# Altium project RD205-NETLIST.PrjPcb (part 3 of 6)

## Sheet 2.SchDoc
size 420 x 297 mm
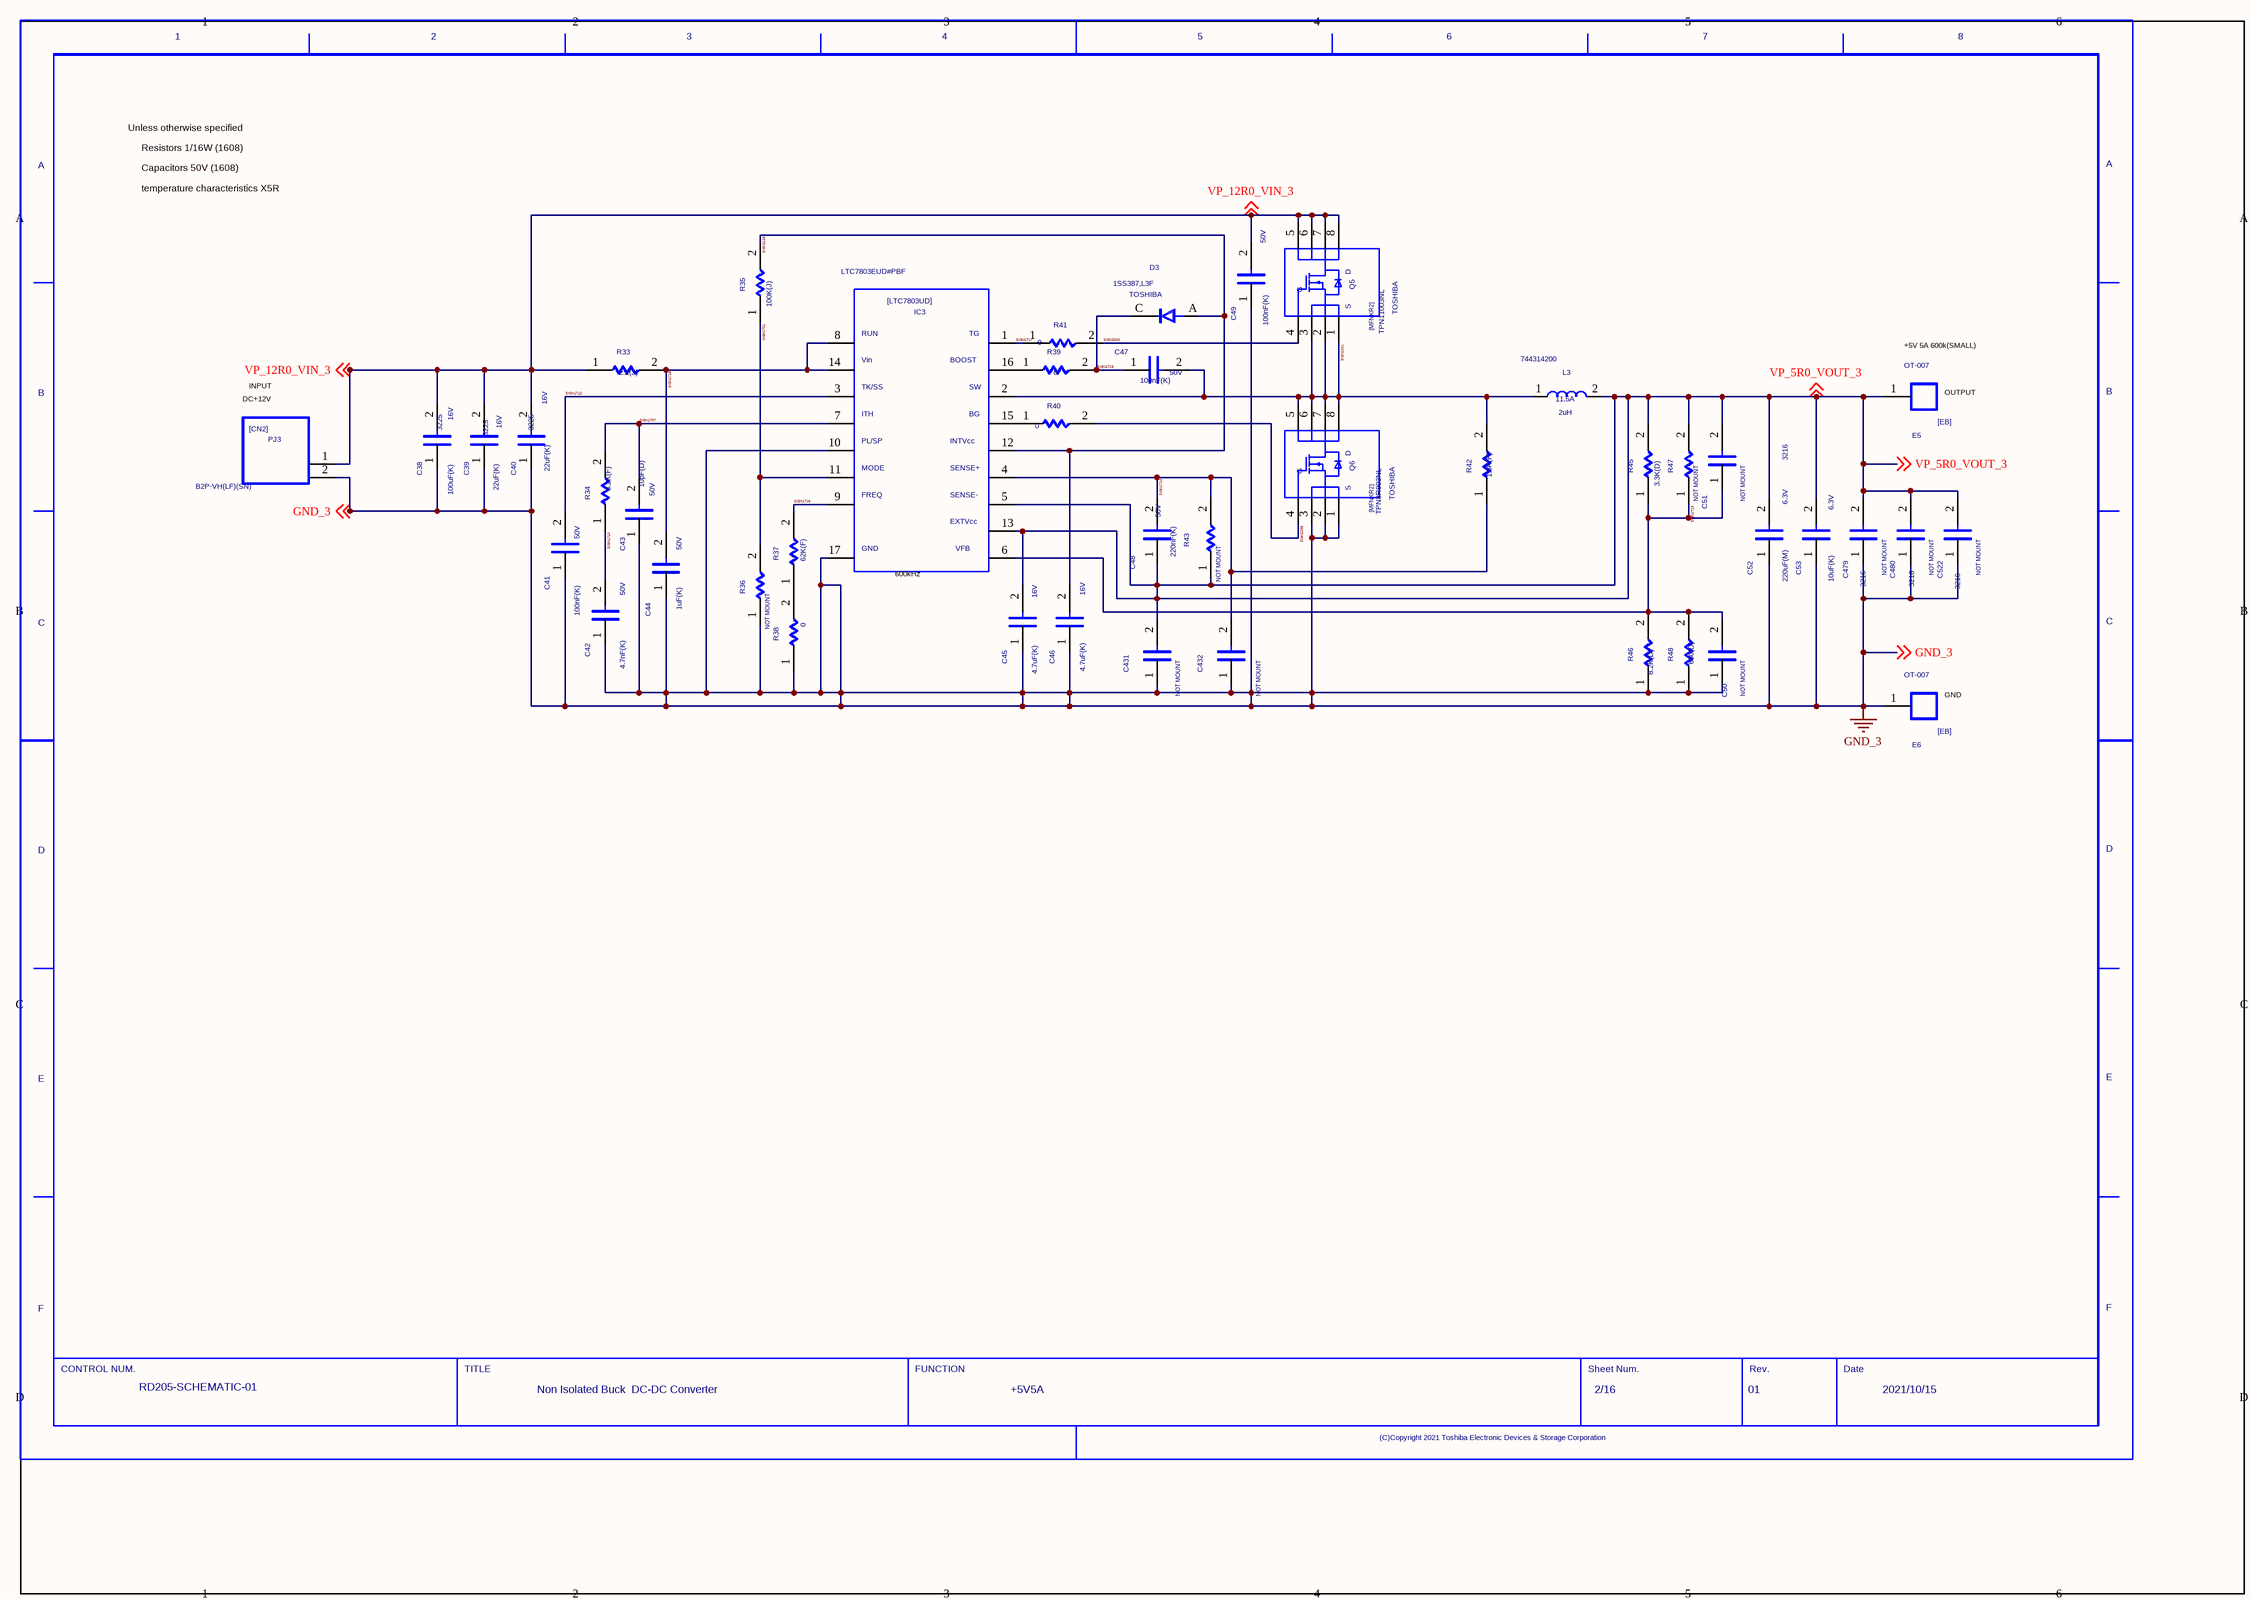
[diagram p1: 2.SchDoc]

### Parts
(Parts that share a designator on the sheet are numbered #1, #2 ... from top to bottom, then left to right.)
C38  SIZECODESMD: 3225  VAL2: 16V  VAL1: 100uF(K)  (hidden comment: C)
C39  SIZECODESMD: 3225  VAL2: 16V  VAL1: 22uF(K)  (hidden comment: C)
C40  SIZECODESMD: 3225  VAL2: 16V  VAL1: 22uF(K)  (hidden comment: C)
C41  VAL2: 50V  VAL1: 100nF(K)  (hidden comment: C)
C42  VAL2: 50V  VAL1: 4.7nF(K)  (hidden comment: C)
C43  VAL2: 50V  VAL1: 10pF(D)  (hidden comment: C)
C44  VAL2: 50V  VAL1: 1uF(K)  (hidden comment: C)
C45  VAL2: 16V  VAL1: 4.7uF(K)  (hidden comment: C)
C46  VAL2: 16V  VAL1: 4.7uF(K)  (hidden comment: C)
C47  VAL2: 50V  VAL1: 100nF(K)  (hidden comment: C)
C48  VAL2: 50V  VAL1: 220nF(K)  (hidden comment: C)
C49  VAL2: 50V  VAL1: 100nF(K)  (hidden comment: C)
C50  NOTMOUNT: NOT MOUNT  (hidden comment: C)
C51  NOTMOUNT: NOT MOUNT  (hidden comment: C)
C52  SIZECODESMD: 3216  VAL2: 6.3V  VAL1: 220uF(M)  (hidden comment: C)
C53  VAL2: 6.3V  VAL1: 10uF(K)  (hidden comment: C)
C431  NOTMOUNT: NOT MOUNT  (hidden comment: C)
C432  NOTMOUNT: NOT MOUNT  (hidden comment: C)
C479  NOTMOUNT: NOT MOUNT  SIZECODESMD: 3216  (hidden comment: C)
C480  NOTMOUNT: NOT MOUNT  SIZECODESMD: 3216  (hidden comment: C)
C522  NOTMOUNT: NOT MOUNT  SIZECODESMD: 3216  (hidden comment: C)
D3  USERCOMPTEXT3: TOSHIBA  VAL3: 1SS387,L3F  (hidden comment: D)
E5  VAL3: OT-007  (hidden comment: EB)
E6  VAL3: OT-007  (hidden comment: EB)
IC3  VAL3: LTC7803EUD#PBF  (hidden comment: LTC7803UD)
L3  VAL3: 744314200  VAL2: 11.5A  VAL1: 2uH  (hidden comment: L)
PJ3  VAL3: B2P-VH(LF)(SN)  (hidden comment: CN2)
Q5  USERCOMPTEXT3: TOSHIBA  VAL3: TPN11003NL  (hidden comment: MFNKR2)
Q6  USERCOMPTEXT3: TOSHIBA  VAL3: TPN8R903NL  (hidden comment: MFNKR2)
R33  VAL1: 2.2(J)  (hidden comment: R)
R34  VAL1: 8.2K(F)  (hidden comment: R)
R35  VAL1: 100K(J)  (hidden comment: R)
R36  NOTMOUNT: NOT MOUNT  (hidden comment: R)
R37  VAL1: 62K(F)  (hidden comment: R)
R38  VAL1: 0  (hidden comment: R)
R39  VAL1: 0  (hidden comment: R)
R40  VAL1: 0  (hidden comment: R)
R41  VAL1: 0  (hidden comment: R)
R42  VAL1: 1.5K(F)  (hidden comment: R)
R43  NOTMOUNT: NOT MOUNT  (hidden comment: R)
R45  VAL1: 3.3K(D)  (hidden comment: R)
R46  VAL1: 8.2K(D)  (hidden comment: R)
R47  NOTMOUNT: NOT MOUNT  (hidden comment: R)
R48  VAL1: 680(D)  (hidden comment: R)
U?#2  DATE: 2021/10/15  SHEETNUMBER: 2/16  TITLE: Non Isolated Buck / DC-DC Converter  REVISION: 01  DRAWINGNUMBER: RD205-SCHEMATIC-01  FUNCTION: +5V5A  (hidden comment: WAKU_DEF100)

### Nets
GND_3: C38.1 C39.1 C40.1 C41.1 C42.1 C43.1 C44.1 C45.1 C46.1 C49.1 C50.1 C52.1 C53.1 C431.1 C432.1 C479.1 C480.1 C522.1 E6.1 IC3.10 IC3.17 PJ3.2 Q6.1 Q6.2 Q6.3 R36.1 R38.1 R46.1 R48.1 ; off-sheet GND_3
SIGN1701: IC3.11 R35.1 R36.2
SIGN1707: C43.2 IC3.7 R34.2
SIGN1710: C42.2 R34.1
SIGN1712: C41.2 IC3.3
SIGN1713: C50.2 C51.1 IC3.6 R45.1 R46.2 R47.1 R48.2
SIGN1714: C48.2 C432.2 IC3.4 R42.1 R43.2
SIGN1716: IC3.9 R37.2
SIGN1717: IC3.1 R41.1
SIGN1718: C44.2 IC3.8 IC3.14 R33.2
SIGN1719: C47.1 D3.C R39.2
SIGN2128: C46.2 D3.A IC3.12 R35.2
SIGN2239: Q6.4 R40.2
SIGN2240: Q5.4 R41.2
SIGN2241: C47.2 IC3.2 L3.1 Q5.1 Q5.2 Q5.3 Q6.5 Q6.6 Q6.7 Q6.8 R42.2
VP_5R0_VOUT_3: C45.2 C48.1 C51.2 C52.2 C53.2 C431.2 C479.2 C480.2 C522.2 E5.1 IC3.5 IC3.13 L3.2 R43.1 R45.2 R47.2 ; off-sheet VP_5R0_VOUT_3
VP_12R0_VIN_3: C38.2 C39.2 C40.2 C49.2 PJ3.1 Q5.5 Q5.6 Q5.7 Q5.8 R33.1 ; off-sheet VP_12R0_VIN_3
NetIC3_15: IC3.15 R40.1
NetIC3_16: IC3.16 R39.1
NetR37_1: R37.1 R38.2

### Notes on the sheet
- Unless otherwise specified
- Capacitors 50V (1608)
- Resistors 1/16W (1608)
- temperature characteristics X5R
- DC+12V
- INPUT
- (near E5) +5V 5A 600k(SMALL)
- (near E5) OUTPUT
- (near IC3) 600kHz
- (near E6) GND

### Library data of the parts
C38 = C_Dup1: SQ_PART_MODEL: CON_100n; FNPARTSNAMEG: CHIP CERAMIC CAPACITOR (3225); USEINPARTSLIST: YES; OriginalSymbolOrigin: (2540,7620); MFSOLDERINGPROP: .; TEMPCHARACTERI2: B; MFFORMINGDIVP: KC; OUMECLASSIFICATION: セラミックコンデンサ; MFMOUNTSYMBOLP: 90; CDMASTERCADCELG: DC903A; PCODE: P03276001115; FNCLASSCODEG: P03-03; MAXGCOUNT: 1; RATEDVOLTAGE: 250; COMPONENTNAME: G36030160049; OUMEMAKER: KYC 京セラ; MFPACKAGEMETHOP: S; NOMINALCAPACITA: 100n; OUMEMAKERKATAMEI: CF32W5R104K250AT; CAPACITANCETOLE: K
C39 C40 = C_Dup1: SQ_PART_MODEL: CON_22u; FNPARTSNAMEG: CHIP CERAMIC CAPACITOR (3225); USEINPARTSLIST: YES; OriginalSymbolOrigin: (2540,7620); MFSOLDERINGPROP: .; TEMPCHARACTERI2: B; MFFORMINGDIVP: KC; OUMECLASSIFICATION: セラミックコンデンサ; MFMOUNTSYMBOLP: 80; CDMASTERCADCELG: DC903A; PCODE: P03043035626; FNCLASSCODEG: P03-03; MAXGCOUNT: 1; RATEDVOLTAGE: 6.3; COMPONENTNAME: G36030119054; OUMEMAKER: TYD 太陽誘電; MFPACKAGEMETHOP: S; NOMINALCAPACITA: 22u; OUMEMAKERKATAMEI: JMK325BJ226KM-T; CAPACITANCETOLE: K
C41 C47 C49 = C_Dup1: SQ_PART_MODEL: CON_100n; FNPARTSNAMEG: CHIP CERAMIC CAPACITOR (1608); USEINPARTSLIST: YES; OriginalSymbolOrigin: (2540,7620); MFSOLDERINGPROP: .; TEMPCHARACTERI2: B; MFFORMINGDIVP: KC; OUMECLASSIFICATION: セラミックコンデンサ; SIZECODESMD: 1608; MFMOUNTSYMBOLP: 80; CDMASTERCADCELG: C8100E; PCODE: P03B000000E4; FNCLASSCODEG: P03-03; MAXGCOUNT: 1; RATEDVOLTAGE: 16; COMPONENTNAME: GDM030000598; OUMEMAKER: MRT 村田製作所; MFPACKAGEMETHOP: S; NOMINALCAPACITA: 100n; OUMEMAKERKATAMEI: GRM188B11C104KA01C; CAPACITANCETOLE: K
C42 = C_Dup1: SQ_PART_MODEL: CON_4.7n; FNPARTSNAMEG: CHIP CERAMIC CAPACITOR (1608); USEINPARTSLIST: YES; OriginalSymbolOrigin: (2540,7620); TOLERANCE: K; ASIMVALUE: 4.7N; MFSOLDERINGPROP: .; TEMPCHARACTERI2: B; MFFORMINGDIVP: KC; OUMECLASSIFICATION: セラミックコンデンサ; SIZECODESMD: 1608; MFMOUNTSYMBOLP: 80; CDMASTERCADCELG: C8100E; PCODE: P03039090226; FNCLASSCODEG: P03-03; MAXGCOUNT: 1; RATEDVOLTAGE: 50; COMPONENTNAME: G36030011280; OUMEMAKER: MRT 村田製作所; MFPACKAGEMETHOP: S; OUMEMAKERKATAMEI: GRM39B472K50PT
C43 = C_Dup1: SQ_PART_MODEL: CON_10p; FNPARTSNAMEG: CHIP CERAMIC CAPACITOR (1608); USEINPARTSLIST: YES; OriginalSymbolOrigin: (2540,7620); TOLERANCE: D; ASIMVALUE: 10P; MFSOLDERINGPROP: .; TEMPCHARACTERI2: CH; MFFORMINGDIVP: KC; OUMECLASSIFICATION: セラミックコンデンサ; SIZECODESMD: 1608; MFMOUNTSYMBOLP: 80; CDMASTERCADCELG: C8100E; PCODE: P03039185229; FNCLASSCODEG: P03-03; MAXGCOUNT: 1; RATEDVOLTAGE: 50; COMPONENTNAME: G36030011013; OUMEMAKER: MRT 村田製作所; MFPACKAGEMETHOP: S; OUMEMAKERKATAMEI: GRM39CH100D50PT
C44 = C_Dup1: SQ_PART_MODEL: CON_1u; FNPARTSNAMEG: CHIP CERAMIC CAPACITOR (1608); USEINPARTSLIST: YES; OriginalSymbolOrigin: (2540,7620); MFSOLDERINGPROP: .; TEMPCHARACTERI2: B; MFFORMINGDIVP: KC; OUMECLASSIFICATION: セラミックコンデンサ; SIZECODESMD: 1608; MFMOUNTSYMBOLP: 80; CDMASTERCADCELG: C8100E; PCODE: P03039ACE122; FNCLASSCODEG: P03-03; MAXGCOUNT: 1; RATEDVOLTAGE: 6.3; COMPONENTNAME: G36030104159; OUMEMAKER: KYC 京セラ; MFPACKAGEMETHOP: S; NOMINALCAPACITA: 1u; OUMEMAKERKATAMEI: CM105B105K06ATN; CAPACITANCETOLE: K
C45 = C_Dup1: SQ_PART_MODEL: CON_4.7u; FNPARTSNAMEG: CHIP CERAMIC CAPACITOR (1608); USEINPARTSLIST: YES; OriginalSymbolOrigin: (2540,7620); PCODE: P03B000000MS; MFSOLDERINGPROP: .; TEMPCHARACTERI2: B; MFFORMINGDIVP: KC; OUMECLASSIFICATION: セラミックコンデンサ; SIZECODESMD: 1608; MFMOUNTSYMBOLP: 80; CDMASTERCADCELG: C8100E; FNCLASSCODEG: P03-03; MAXGCOUNT: 1; RATEDVOLTAGE: 4; COMPONENTNAME: GDM030000053; OUMEMAKER: KYC 京セラ; MFPACKAGEMETHOP: S; NOMINALCAPACITA: 4.7u; OUMEMAKERKATAMEI: CM105B475M04AT; CAPACITANCETOLE: M
C46 = C_Dup1: SQ_PART_MODEL: CON_4.7u; FNPARTSNAMEG: CHIP CERAMIC CAPACITOR (1608); USEINPARTSLIST: YES; OriginalSymbolOrigin: (2540,7620); MFSOLDERINGPROP: .; TEMPCHARACTERI2: B; MFFORMINGDIVP: KC; OUMECLASSIFICATION: セラミックコンデンサ; SIZECODESMD: 1608; MFMOUNTSYMBOLP: 80; CDMASTERCADCELG: C8100E; PCODE: P03B000000MS; FNCLASSCODEG: P03-03; MAXGCOUNT: 1; RATEDVOLTAGE: 4; COMPONENTNAME: GDM030000053; OUMEMAKER: KYC 京セラ; MFPACKAGEMETHOP: S; NOMINALCAPACITA: 4.7u; OUMEMAKERKATAMEI: CM105B475M04AT; CAPACITANCETOLE: M
C48 = C_Dup1: SQ_PART_MODEL: CON_220n; FNPARTSNAMEG: CHIP CERAMIC CAPACITOR (1608); PARTCOMMENT: 代表セル<KC0008> がフットプリントに登録されていません。; USEINPARTSLIST: YES; OriginalSymbolOrigin: (2540,7620); MFSOLDERINGPROP: .; TEMPCHARACTERI2: B; MFFORMINGDIVP: KC; OUMECLASSIFICATION: セラミックコンデンサ; SIZECODESMD: 1608; MFMOUNTSYMBOLP: 80; CDMASTERCADCELG: KC0008; PCODE: P03B000001L3; FNCLASSCODEG: P03-03; MAXGCOUNT: 1; RATEDVOLTAGE: 16; COMPONENTNAME: GDM030001129; OUMEMAKER: MRT 村田製作所; MFPACKAGEMETHOP: S; NOMINALCAPACITA: 220n; OUMEMAKERKATAMEI: GRM188B11C224KA01D; CAPACITANCETOLE: K
C50 C51 = C_Dup1: SQ_PART_MODEL: CON_100p; FNPARTSNAMEG: CHIP CERAMIC CAPACITOR (1608); USEINPARTSLIST: YES; OriginalSymbolOrigin: (2540,7620); TOLERANCE: J; ASIMVALUE: 100P; MFSOLDERINGPROP: .; TEMPCHARACTERI2: CH; MFFORMINGDIVP: KC; OUMECLASSIFICATION: セラミックコンデンサ; SIZECODESMD: 1608; MFMOUNTSYMBOLP: 80; CDMASTERCADCELG: C8100E; PCODE: P03039177125; FNCLASSCODEG: P03-03; MAXGCOUNT: 1; RATEDVOLTAGE: 50; COMPONENTNAME: G36030011365; OUMEMAKER: KYC 京セラ; MFPACKAGEMETHOP: S; OUMEMAKERKATAMEI: CM105CH101J50AT; VAL2: 50V; VAL1: 100pF(J)
C52 = C_Dup1: SQ_PART_MODEL: CON_22u; FNPARTSNAMEG: CHIP CERAMIC CAPACITOR (3216); USEINPARTSLIST: YES; OriginalSymbolOrigin: (2540,7620); MFSOLDERINGPROP: .; TEMPCHARACTERI2: B; MFFORMINGDIVP: KC; OUMECLASSIFICATION: セラミックコンデンサ; MFMOUNTSYMBOLP: 80; CDMASTERCADCELG: DC901A; PCODE: P03B0000004V; FNCLASSCODEG: P03-03; MAXGCOUNT: 1; RATEDVOLTAGE: 6.3; COMPONENTNAME: GDM030000020; OUMEMAKER: KYC 京セラ; MFPACKAGEMETHOP: S; NOMINALCAPACITA: 22u; OUMEMAKERKATAMEI: CM316B226M06AT; CAPACITANCETOLE: M
C53 = C_Dup1: SQ_PART_MODEL: CON_1u; FNPARTSNAMEG: CHIP CERAMIC CAPACITOR (1608); PARTCOMMENT: 代表セル<KC0008> がフットプリントに登録されていません。; USEINPARTSLIST: YES; OriginalSymbolOrigin: (2540,7620); MFSOLDERINGPROP: .; TEMPCHARACTERI2: B; MFPACKAGEMETHOP: S; MFFORMINGDIVP: KC; MFMOUNTSYMBOLP: 80; PCODE: P03B000000ZQ; OUMECLASSIFICATION: セラミックコンデンサ; SIZECODESMD: 1608; CDMASTERCADCELG: KC0008; FNCLASSCODEG: P03-03; MAXGCOUNT: 1; RATEDVOLTAGE: 6.3; COMPONENTNAME: GDM030000202; OUMEMAKER: MRT 村田製作所; NOMINALCAPACITA: 1u; OUMEMAKERKATAMEI: GRM185B10J105KE21D; CAPACITANCETOLE: K
C431 C432 = C_Dup1: SQ_PART_MODEL: CON_220n; FNPARTSNAMEG: CHIP CERAMIC CAPACITOR (1608); PARTCOMMENT: 代表セル<KC0008> がフットプリントに登録されていません。; USEINPARTSLIST: YES; OriginalSymbolOrigin: (2540,7620); MFSOLDERINGPROP: .; TEMPCHARACTERI2: B; MFFORMINGDIVP: KC; OUMECLASSIFICATION: セラミックコンデンサ; SIZECODESMD: 1608; MFMOUNTSYMBOLP: 80; CDMASTERCADCELG: KC0008; PCODE: P03B000001L3; FNCLASSCODEG: P03-03; MAXGCOUNT: 1; RATEDVOLTAGE: 16; COMPONENTNAME: GDM030001129; OUMEMAKER: MRT 村田製作所; MFPACKAGEMETHOP: S; NOMINALCAPACITA: 220n; OUMEMAKERKATAMEI: GRM188B11C224KA01D; VAL2: 16V; VAL1: 220nF(K); CAPACITANCETOLE: K
C479 C480 C522 = C_Dup1: SQ_PART_MODEL: CON_22u; FNPARTSNAMEG: CHIP CERAMIC CAPACITOR (3216); USEINPARTSLIST: YES; OriginalSymbolOrigin: (2540,7620); MFSOLDERINGPROP: .; TEMPCHARACTERI2: B; MFFORMINGDIVP: KC; OUMECLASSIFICATION: セラミックコンデンサ; MFMOUNTSYMBOLP: 80; CDMASTERCADCELG: DC901A; PCODE: P03B0000004V; FNCLASSCODEG: P03-03; MAXGCOUNT: 1; RATEDVOLTAGE: 6.3; COMPONENTNAME: GDM030000020; OUMEMAKER: KYC 京セラ; MFPACKAGEMETHOP: S; NOMINALCAPACITA: 22u; OUMEMAKERKATAMEI: CM316B226M06AT; VAL2: 6.3V; VAL1: 22uF(M); CAPACITANCETOLE: M
D3 = D_Dup1: FNPARTSNAMEG: DIODE; USEINPARTSLIST: YES; PARTNAME: GDM420000143; SAVEAREA0: -565,-171,12979,8058; SAVECOUNT: 1; OriginalSymbolOrigin: (2540,5080); FORWARDVOLTAGEM: 0; MAXREVERSEVOLTA: 80; COMPONENTNAME: GDM420000143_package; MFSOLDERINGPROP: .; OUMEMAKER: TSB 東芝（ＹＰＳＳ）; QUADMODEL: dummymodel; MFPACKAGEMETHOP: S; MFFORMINGDIVP: MM; MOUNTINGFORMSMD: SMD; OUMECLASSIFICATION: 小信号ダイオード; OUMEMAKERKATAMEI: 1SS387(TPH3,F); CDMASTERCADCELG: D8101D; PCODE: P42B0000008E; FNCLASSCODEG: P42-01
E5 E6 = EB_Dup1: FNPARTSNAMEG: TERMINAL; USEINPARTSLIST: YES; PARTNAME: 5P9L1232P001; OUMEPARTTYPE: TB; OriginalSymbolOrigin: (2540,12700); COMPONENTNAME: 5P9L1232P001_package; MAXGCOUNT: 1; MFSOLDERINGPROP: .; OUMEMAKER: オサダ; QUADMODEL: dummymodel; MFPACKAGEMETHOP: I; MFFORMINGDIVP: OD; OUMECLASSIFICATION: 端子台、端子板; CDMASTERCADCELG: DE0009; KIND: PBS; PCODE: P29045001117; TERMINALSTYLE: SC; FNCLASSCODEG: P29-01
IC3 = LTC7803UD: USEINPARTSLIST: YES; SAVECOUNT: 29; SAVEAREA0: -53177,0,89020,58420; TIME: 16:14:14; UPDATEUSER: q91866sr; UPDATETIME: 13:15:36; OriginalSymbolOrigin: (5080,55880); MAXGCOUNT: 1; COMPONENTNAME: LTC7803UD_LTC7803UD; OUMEMAKER: ANALOG DEVICES
L3 = L_Dup1: USEINPARTSLIST: YES; PARTNAME: 744311100; OriginalSymbolOrigin: (2540,5080); MAXGCOUNT: 1; COMPONENTNAME: L_L; OUMEMAKER: WURTH
PJ3 = CN2_Dup1: FNPARTSNAMEG: 3.96PITCH NYLON CONNECTOR; USEINPARTSLIST: YES; PARTNAME: G36220114012; OUMEPARTTYPE: CN; OriginalSymbolOrigin: (2540,15240); MAXGCOUNT: 1; RATEDCURRENT: 7; COMPONENTNAME: G36220114012_package; MFSOLDERINGPROP: .; OUMEMAKER: JST 日本圧着端子製造; NUMBEROFCONTACT: 2; QUADMODEL: dummymodel; MFPACKAGEMETHOP: I; MFFORMINGDIVP: CU; CONTACTPITCH: 3.96m; OUMEMAKERKATAMEI: B2P-VH; CDMASTERCADCELG: DPJ514; PCODE: P22346001114; TERMINALSTYLE: PW; FNCLASSCODEG: P22-10
Q5 Q6 = MFNKR2: USEINPARTSLIST: YES; PARTNAME: TPN1R603PL; SAVEAREA0: -9199,-39,32138,22820; TIME: 18:57:44; UPDATEUSER: q91866sr; UPDATETIME: 12:36:02; SAVECOUNT: 10; OriginalSymbolOrigin: (5080,20320); MAXGCOUNT: 1; COMPONENTNAME: MFNKR2_MFNKR2
R33 = R_Dup1: SQ_PART_MODEL: RES_2.2; FNPARTSNAMEG: CHIP RESISTOR (1608); USEINPARTSLIST: YES; OriginalSymbolOrigin: (5080,5080); TOLERANCE: J; ASIMVALUE: 2.2; MAXGCOUNT: 1; COMPONENTNAME: G36010011507; MFSOLDERINGPROP: .; OUMEMAKER: NAE 松下電子部品; MFPACKAGEMETHOP: S; MFFORMINGDIVP: KC; MOUNTINGFORMSMD: SMD; OUMECLASSIFICATION: 表面実装用固定抵抗器; MFMOUNTSYMBOLP: 80; POWERRATING: 63m; OUMEMAKERKATAMEI: ERJ3GEYJ2R2V; NUMBEROFELEMENT: 0; VAL2: 62.5mW; CDMASTERCADCELG: DR802R; PCODE: P01042157622; FNCLASSCODEG: P01-08
R34 = R_Dup1: SQ_PART_MODEL: RES_8.2K; FNPARTSNAMEG: CHIP RESISTOR (1608); USEINPARTSLIST: YES; OriginalSymbolOrigin: (5080,5080); TOLERANCE: F; ASIMVALUE: 8.2K; MAXGCOUNT: 1; COMPONENTNAME: G36010027188; MFSOLDERINGPROP: .; OUMEMAKER: KAM 釜屋電機; MFPACKAGEMETHOP: S; MFFORMINGDIVP: KC; MOUNTINGFORMSMD: SMD; OUMECLASSIFICATION: 表面実装用固定抵抗器; MFMOUNTSYMBOLP: 80; POWERRATING: 63m; OUMEMAKERKATAMEI: RMC1/16-822FTP; NUMBEROFELEMENT: 0; VAL2: 62.5mW; CDMASTERCADCELG: DR802R; PCODE: P01042507328; FNCLASSCODEG: P01-08
R35 = R_Dup1: SQ_PART_MODEL: RES_100K; FNPARTSNAMEG: CHIP RESISTOR (1608); USEINPARTSLIST: YES; OriginalSymbolOrigin: (5080,5080); TOLERANCE: J; ASIMVALUE: 100K; MFSOLDERINGPROP: .; MFPACKAGEMETHOP: S; MFFORMINGDIVP: KC; MOUNTINGFORMSMD: SMD; MFMOUNTSYMBOLP: 80; NUMBEROFELEMENT: 0; PCODE: P01042047220; MAXGCOUNT: 1; COMPONENTNAME: G36010011057; OUMEMAKER: HDK 北陸電気工業; OUMECLASSIFICATION: 表面実装用固定抵抗器; POWERRATING: 63m; OUMEMAKERKATAMEI: CR1/16 104JV; VAL2: 62.5mW; CDMASTERCADCELG: DR802R; FNCLASSCODEG: P01-08
R36 = R_Dup1: SQ_PART_MODEL: RES_10; FNPARTSNAMEG: CHIP RESISTOR (1608); USEINPARTSLIST: YES; OriginalSymbolOrigin: (5080,5080); TOLERANCE: F; ASIMVALUE: 10; MFSOLDERINGPROP: .; MFPACKAGEMETHOP: S; MFFORMINGDIVP: KC; MOUNTINGFORMSMD: SMD; MFMOUNTSYMBOLP: 80; NUMBEROFELEMENT: 0; PCODE: P01042036620; MAXGCOUNT: 1; COMPONENTNAME: G36010104063; OUMEMAKER: NAE 松下電子部品; OUMECLASSIFICATION: 表面実装用固定抵抗器; POWERRATING: 63m; OUMEMAKERKATAMEI: ERJ3GEYF100V; VAL2: 62.5mW; VAL1: 10(F); CDMASTERCADCELG: DR802R; FNCLASSCODEG: P01-08
R37 = R_Dup1: SQ_PART_MODEL: RES_62K; FNPARTSNAMEG: CHIP RESISTOR (1608); USEINPARTSLIST: YES; OriginalSymbolOrigin: (5080,5080); MAXGCOUNT: 1; TOLERANCE: F; COMPONENTNAME: G36010027355; MFSOLDERINGPROP: .; OUMEMAKER: HDK 北陸電気工業; MFPACKAGEMETHOP: S; MFFORMINGDIVP: KC; MOUNTINGFORMSMD: SMD; OUMECLASSIFICATION: 表面実装用固定抵抗器; ASIMVALUE: 62K; MFMOUNTSYMBOLP: 80; POWERRATING: 63m; OUMEMAKERKATAMEI: CR1/16 623FV; NUMBEROFELEMENT: 0; VAL2: 62.5mW; CDMASTERCADCELG: DR802R; PCODE: P01042441226; FNCLASSCODEG: P01-08
R38 = R_Dup1: SQ_PART_MODEL: RES_10; FNPARTSNAMEG: CHIP RESISTOR (1608); USEINPARTSLIST: YES; OriginalSymbolOrigin: (5080,5080); TOLERANCE: F; ASIMVALUE: 10; MAXGCOUNT: 1; COMPONENTNAME: G36010104063; MFSOLDERINGPROP: .; OUMEMAKER: NAE 松下電子部品; MFPACKAGEMETHOP: S; MFFORMINGDIVP: KC; MOUNTINGFORMSMD: SMD; OUMECLASSIFICATION: 表面実装用固定抵抗器; MFMOUNTSYMBOLP: 80; POWERRATING: 63m; OUMEMAKERKATAMEI: ERJ3GEYF100V; VAL2: 62.5mW; CDMASTERCADCELG: DR802R; PCODE: P01042036620; FNCLASSCODEG: P01-08
R39 = R_Dup1: SQ_PART_MODEL: RES_10; FNPARTSNAMEG: CHIP RESISTOR (1608); USEINPARTSLIST: YES; OriginalSymbolOrigin: (5080,5080); TOLERANCE: F; ASIMVALUE: 10; MFSOLDERINGPROP: .; MFPACKAGEMETHOP: S; MFFORMINGDIVP: KC; MOUNTINGFORMSMD: SMD; MFMOUNTSYMBOLP: 80; PCODE: P01042036620; MAXGCOUNT: 1; COMPONENTNAME: G36010104063; OUMEMAKER: NAE 松下電子部品; OUMECLASSIFICATION: 表面実装用固定抵抗器; POWERRATING: 63m; OUMEMAKERKATAMEI: ERJ3GEYF100V; VAL2: 62.5mW; CDMASTERCADCELG: DR802R; FNCLASSCODEG: P01-08
R40 R41 = R_Dup1: SQ_PART_MODEL: RES_10; FNPARTSNAMEG: CHIP RESISTOR (2012); USEINPARTSLIST: YES; OriginalSymbolOrigin: (5080,5080); MAXGCOUNT: 1; TOLERANCE: F; COMPONENTNAME: 5P9L1083P100; MFSOLDERINGPROP: .; OUMEMAKER: 北陸電気工業; MFPACKAGEMETHOP: S; MFFORMINGDIVP: KC; MOUNTINGFORMSMD: SMD; OUMECLASSIFICATION: 表面実装用固定抵抗器; ASIMVALUE: 10; MFMOUNTSYMBOLP: 90; POWERRATING: 100m; OUMEMAKERKATAMEI: CR1/10 100FV Pb(F); VAL2: 125mW; CDMASTERCADCELG: DR910A; PCODE: P01043091222; FNCLASSCODEG: P01-08
R42 = R_Dup1: SQ_PART_MODEL: RES_1.5K; FNPARTSNAMEG: CHIP RESISTOR (1608); USEINPARTSLIST: YES; OriginalSymbolOrigin: (5080,5080); TOLERANCE: F; ASIMVALUE: 1.5K; MAXGCOUNT: 1; COMPONENTNAME: G36010027232; MFSOLDERINGPROP: .; OUMEMAKER: HDK 北陸電気工業; MFPACKAGEMETHOP: S; MFFORMINGDIVP: KC; MOUNTINGFORMSMD: SMD; OUMECLASSIFICATION: 表面実装用固定抵抗器; MFMOUNTSYMBOLP: 80; POWERRATING: 63m; OUMEMAKERKATAMEI: CR1/16 152FV; NUMBEROFELEMENT: 0; VAL2: 62.5mW; CDMASTERCADCELG: DR802R; PCODE: P01042512223; FNCLASSCODEG: P01-08
R43 = R_Dup1: SQ_PART_MODEL: RES_8.2K; FNPARTSNAMEG: CHIP RESISTOR (1608); USEINPARTSLIST: YES; OriginalSymbolOrigin: (5080,5080); TOLERANCE: F; ASIMVALUE: 8.2K; MAXGCOUNT: 1; COMPONENTNAME: G36010027188; MFSOLDERINGPROP: .; OUMEMAKER: KAM 釜屋電機; MFPACKAGEMETHOP: S; MFFORMINGDIVP: KC; MOUNTINGFORMSMD: SMD; OUMECLASSIFICATION: 表面実装用固定抵抗器; MFMOUNTSYMBOLP: 80; POWERRATING: 63m; OUMEMAKERKATAMEI: RMC1/16-822FTP; NUMBEROFELEMENT: 0; VAL2: 62.5mW; VAL1: 8.2K(F); CDMASTERCADCELG: DR802R; PCODE: P01042507328; FNCLASSCODEG: P01-08
R45 = R_Dup1: SQ_PART_MODEL: RES_3.3K; FNPARTSNAMEG: CHIP RESISTOR (1608); USEINPARTSLIST: YES; OriginalSymbolOrigin: (5080,5080); MAXGCOUNT: 1; COMPONENTNAME: G36010014485; MFSOLDERINGPROP: .; OUMEMAKER: SSM 進工業; MFPACKAGEMETHOP: S; MFFORMINGDIVP: KC; MOUNTINGFORMSMD: SMD; OUMECLASSIFICATION: 表面実装用固定抵抗器; RESISTANCETOLER: D; MFMOUNTSYMBOLP: 80; POWERRATING: 63m; OUMEMAKERKATAMEI: RR0816P-332-D; NOMINALRESISTAN: 3.3K; NUMBEROFELEMENT: 0; VAL2: 62.5mW; CDMASTERCADCELG: DR802R; PCODE: P01042249822; FNCLASSCODEG: P01-08
R46 = R_Dup1: ICX_PART_MODEL: RES_8.2K; FNPARTSNAMEG: CHIP RESISTOR (1608); OriginalSymbolOrigin: (5080,5080); FNCLASSCODEG: P01-08; PCODE: P01117051114; CDMASTERCADCELG: DR802R; USEWITHSCHEMA: YES; VAL2: 62.5mW; NUMBEROFELEMENT: 0; NOMINALRESISTAN: 8.2K; OUMEMAKERKATAMEI: RK73G1JTD822D; POWERRATING: 63m; MFMOUNTSYMBOLP: 80; RESISTANCETOLER: D; FUNCTION: G36010129479; OUMECLASSIFICATION: 表面実装用固定抵抗器; MOUNTINGFORMSMD: SMD; MFFORMINGDIVP: KC; MFPACKAGEMETHOP: S; OUMEMAKER: KOA ＫＯＡ; MFSOLDERINGPROP: .; MAXGCOUNT: 1
R47 = R_Dup1: SQ_PART_MODEL: RES_3.3K; FNPARTSNAMEG: CHIP RESISTOR (1608); USEINPARTSLIST: YES; OriginalSymbolOrigin: (5080,5080); TOLERANCE: F; ASIMVALUE: 3.3K; MAXGCOUNT: 1; COMPONENTNAME: G36010027027; MFSOLDERINGPROP: .; OUMEMAKER: ROH ロー・; MFPACKAGEMETHOP: S; MFFORMINGDIVP: KC; MOUNTINGFORMSMD: SMD; OUMECLASSIFICATION: 表面実装用固定抵抗器; MFMOUNTSYMBOLP: 80; POWERRATING: 63m; OUMEMAKERKATAMEI: MCR03EZPFX3301; NUMBEROFELEMENT: 0; VAL2: 62.5mW; VAL1: 3.3K(F); CDMASTERCADCELG: DR802R; PCODE: P01042250729; FNCLASSCODEG: P01-08
R48 = R_Dup1: ICX_PART_MODEL: RES_680; FNPARTSNAMEG: CHIP RESISTOR (1608); OriginalSymbolOrigin: (5080,5080); FNCLASSCODEG: P01-08; PCODE: P01117025115; CDMASTERCADCELG: DR802R; USEWITHSCHEMA: YES; VAL2: 62.5mW; NUMBEROFELEMENT: 0; NOMINALRESISTAN: 680; OUMEMAKERKATAMEI: RK73G1JTD681D; POWERRATING: 63m; MFMOUNTSYMBOLP: 80; RESISTANCETOLER: D; FUNCTION: G36010129219; OUMECLASSIFICATION: 表面実装用固定抵抗器; MOUNTINGFORMSMD: SMD; MFFORMINGDIVP: KC; MFPACKAGEMETHOP: S; OUMEMAKER: KOA ＫＯＡ; MFSOLDERINGPROP: .; MAXGCOUNT: 1
U?#2 = WAKU_DEF100: PLOTTIME: HH:MM; SAVEAREA0: 330961,54,387907,31546; TIME: 19:23:07; UPDATEUSER: t5459927; UPDATETIME: 15:33:38; SAVECOUNT: 6; OriginalSymbolOrigin: (10160,284480); DESIGNED: ***

## Sheet 3.SchDoc
size 420 x 297 mm
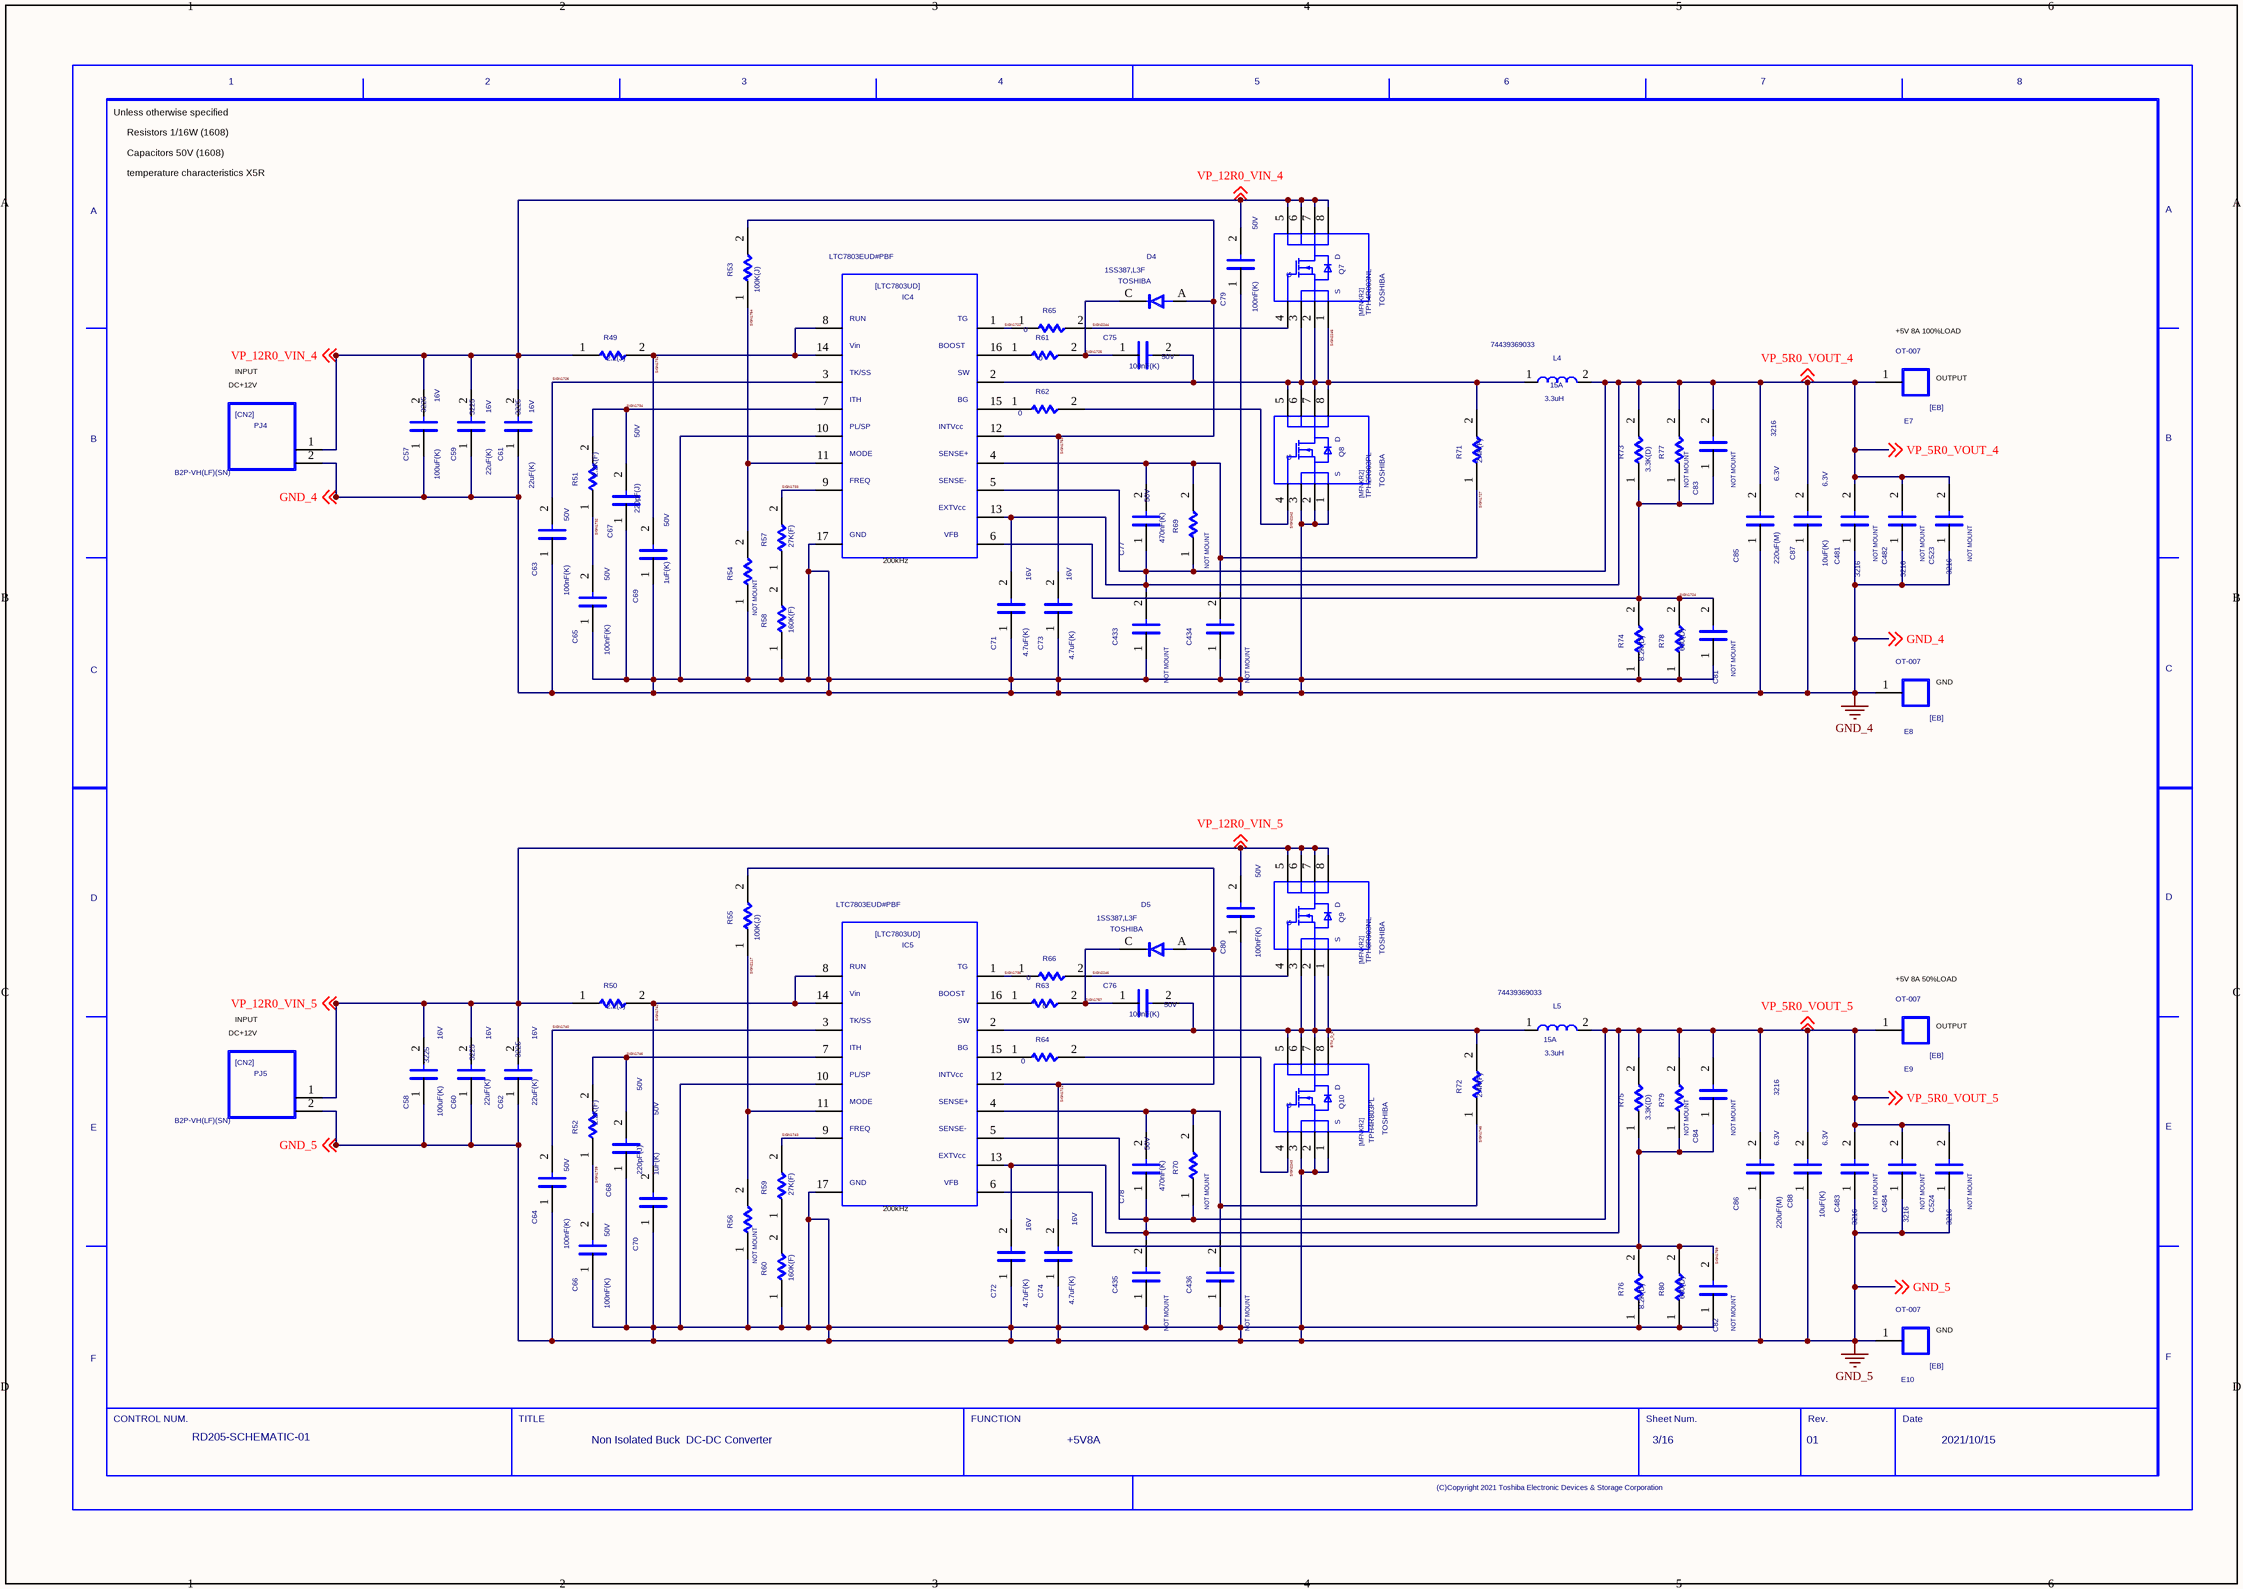
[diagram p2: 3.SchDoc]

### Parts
(Parts that share a designator on the sheet are numbered #1, #2 ... from top to bottom, then left to right.)
C57  SIZECODESMD: 3225  VAL2: 16V  VAL1: 100uF(K)  (hidden comment: C)
C58  SIZECODESMD: 3225  VAL2: 16V  VAL1: 100uF(K)  (hidden comment: C)
C59  SIZECODESMD: 3225  VAL2: 16V  VAL1: 22uF(K)  (hidden comment: C)
C60  SIZECODESMD: 3225  VAL2: 16V  VAL1: 22uF(K)  (hidden comment: C)
C61  SIZECODESMD: 3225  VAL2: 16V  VAL1: 22uF(K)  (hidden comment: C)
C62  SIZECODESMD: 3225  VAL2: 16V  VAL1: 22uF(K)  (hidden comment: C)
C63  VAL2: 50V  VAL1: 100nF(K)  (hidden comment: C)
C64  VAL2: 50V  VAL1: 100nF(K)  (hidden comment: C)
C65  VAL2: 50V  VAL1: 100nF(K)  (hidden comment: C)
C66  VAL2: 50V  VAL1: 100nF(K)  (hidden comment: C)
C67  VAL2: 50V  VAL1: 220pF(J)  (hidden comment: C)
C68  VAL2: 50V  VAL1: 220pF(J)  (hidden comment: C)
C69  VAL2: 50V  VAL1: 1uF(K)  (hidden comment: C)
C70  VAL2: 50V  VAL1: 1uF(K)  (hidden comment: C)
C71  VAL2: 16V  VAL1: 4.7uF(K)  (hidden comment: C)
C72  VAL2: 16V  VAL1: 4.7uF(K)  (hidden comment: C)
C73  VAL2: 16V  VAL1: 4.7uF(K)  (hidden comment: C)
C74  VAL2: 16V  VAL1: 4.7uF(K)  (hidden comment: C)
C75  VAL2: 50V  VAL1: 100nF(K)  (hidden comment: C)
C76  VAL2: 50V  VAL1: 100nF(K)  (hidden comment: C)
C77  VAL2: 50V  VAL1: 470nF(K)  (hidden comment: C)
C78  VAL2: 50V  VAL1: 470nF(K)  (hidden comment: C)
C79  VAL2: 50V  VAL1: 100nF(K)  (hidden comment: C)
C80  VAL2: 50V  VAL1: 100nF(K)  (hidden comment: C)
C81  NOTMOUNT: NOT MOUNT  (hidden comment: C)
C82  NOTMOUNT: NOT MOUNT  (hidden comment: C)
C83  NOTMOUNT: NOT MOUNT  (hidden comment: C)
C84  NOTMOUNT: NOT MOUNT  (hidden comment: C)
C85  SIZECODESMD: 3216  VAL2: 6.3V  VAL1: 220uF(M)  (hidden comment: C)
C86  SIZECODESMD: 3216  VAL2: 6.3V  VAL1: 220uF(M)  (hidden comment: C)
C87  VAL2: 6.3V  VAL1: 10uF(K)  (hidden comment: C)
C88  VAL2: 6.3V  VAL1: 10uF(K)  (hidden comment: C)
C433  NOTMOUNT: NOT MOUNT  (hidden comment: C)
C434  NOTMOUNT: NOT MOUNT  (hidden comment: C)
C435  NOTMOUNT: NOT MOUNT  (hidden comment: C)
C436  NOTMOUNT: NOT MOUNT  (hidden comment: C)
C481  NOTMOUNT: NOT MOUNT  SIZECODESMD: 3216  (hidden comment: C)
C482  NOTMOUNT: NOT MOUNT  SIZECODESMD: 3216  (hidden comment: C)
C483  NOTMOUNT: NOT MOUNT  SIZECODESMD: 3216  (hidden comment: C)
C484  NOTMOUNT: NOT MOUNT  SIZECODESMD: 3216  (hidden comment: C)
C523  NOTMOUNT: NOT MOUNT  SIZECODESMD: 3216  (hidden comment: C)
C524  NOTMOUNT: NOT MOUNT  SIZECODESMD: 3216  (hidden comment: C)
D4  USERCOMPTEXT3: TOSHIBA  VAL3: 1SS387,L3F  (hidden comment: D)
D5  USERCOMPTEXT3: TOSHIBA  VAL3: 1SS387,L3F  (hidden comment: D)
E7  VAL3: OT-007  (hidden comment: EB)
E8  VAL3: OT-007  (hidden comment: EB)
E9  VAL3: OT-007  (hidden comment: EB)
E10  VAL3: OT-007  (hidden comment: EB)
IC4  VAL3: LTC7803EUD#PBF  (hidden comment: LTC7803UD)
IC5  VAL3: LTC7803EUD#PBF  (hidden comment: LTC7803UD)
L4  VAL3: 74439369033  VAL2: 15A  VAL1: 3.3uH  (hidden comment: L)
L5  VAL3: 74439369033  VAL2: 15A  VAL1: 3.3uH  (hidden comment: L)
PJ4  VAL3: B2P-VH(LF)(SN)  (hidden comment: CN2)
PJ5  VAL3: B2P-VH(LF)(SN)  (hidden comment: CN2)
Q7  USERCOMPTEXT3: TOSHIBA  VAL3: TPH4R003NL  (hidden comment: MFNKR2)
Q8  USERCOMPTEXT3: TOSHIBA  VAL3: TPH2R903PL  (hidden comment: MFNKR2)
Q9  USERCOMPTEXT3: TOSHIBA  VAL3: TPH8R903NL  (hidden comment: MFNKR2)
Q10  USERCOMPTEXT3: TOSHIBA  VAL3: TPH4R803PL  (hidden comment: MFNKR2)
R49  VAL1: 2.2(J)  (hidden comment: R)
R50  VAL1: 2.2(J)  (hidden comment: R)
R51  VAL1: 2.2K(F)  (hidden comment: R)
R52  VAL1: 2.2K(F)  (hidden comment: R)
R53  VAL1: 100K(J)  (hidden comment: R)
R54  NOTMOUNT: NOT MOUNT  (hidden comment: R)
R55  VAL1: 100K(J)  (hidden comment: R)
R56  NOTMOUNT: NOT MOUNT  (hidden comment: R)
R57  VAL1: 27K(F)  (hidden comment: R)
R58  VAL1: 160K(F)  (hidden comment: R)
R59  VAL1: 27K(F)  (hidden comment: R)
R60  VAL1: 160K(F)  (hidden comment: R)
R61  VAL1: 0  (hidden comment: R)
R62  VAL1: 0  (hidden comment: R)
R63  VAL1: 0  (hidden comment: R)
R64  VAL1: 0  (hidden comment: R)
R65  VAL1: 0  (hidden comment: R)
R66  VAL1: 0  (hidden comment: R)
R69  NOTMOUNT: NOT MOUNT  (hidden comment: R)
R70  NOTMOUNT: NOT MOUNT  (hidden comment: R)
R71  VAL1: 2.4K(F)  (hidden comment: R)
R72  VAL1: 2.4K(F)  (hidden comment: R)
R73  VAL1: 3.3K(D)  (hidden comment: R)
R74  VAL1: 8.2K(D)  (hidden comment: R)
R75  VAL1: 3.3K(D)  (hidden comment: R)
R76  VAL1: 8.2K(D)  (hidden comment: R)
R77  NOTMOUNT: NOT MOUNT  (hidden comment: R)
R78  VAL1: 680(D)  (hidden comment: R)
R79  NOTMOUNT: NOT MOUNT  (hidden comment: R)
R80  VAL1: 680(D)  (hidden comment: R)
U?#3  DATE: 2021/10/15  SHEETNUMBER: 3/16  TITLE: Non Isolated Buck / DC-DC Converter  REVISION: 01  DRAWINGNUMBER: RD205-SCHEMATIC-01  FUNCTION: +5V8A  (hidden comment: WAKU_DEF100)

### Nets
GND_4: C57.1 C59.1 C61.1 C63.1 C65.1 C67.1 C69.1 C71.1 C73.1 C79.1 C81.1 C85.1 C87.1 C433.1 C434.1 C481.1 C482.1 C523.1 E8.1 IC4.10 IC4.17 PJ4.2 Q8.1 Q8.2 Q8.3 R54.1 R58.1 R74.1 R78.1 ; off-sheet GND_4
GND_5: C58.1 C60.1 C62.1 C64.1 C66.1 C68.1 C70.1 C72.1 C74.1 C80.1 C82.1 C86.1 C88.1 C435.1 C436.1 C483.1 C484.1 C524.1 E10.1 IC5.10 IC5.17 PJ5.2 Q10.1 Q10.2 Q10.3 R56.1 R60.1 R76.1 R80.1 ; off-sheet GND_5
BTM_D_5: C76.2 IC5.2 L5.1 Q9.1 Q9.2 Q9.3 Q10.5 Q10.6 Q10.7 Q10.8 R72.2
SIGN1721: C74.2 D5.A IC5.12 R55.2
SIGN1722: IC4.1 R65.1
SIGN1724: C81.2 C83.1 IC4.6 R73.1 R74.2 R77.1 R78.2
SIGN1725: C75.1 D4.C R61.2
SIGN1726: C63.2 IC4.3
SIGN1727: C77.2 C434.2 IC4.4 R69.2 R71.1
SIGN1731: C69.2 IC4.8 IC4.14 R49.2
SIGN1732: C65.2 R51.1
SIGN1733: IC4.9 R57.2
SIGN1734: C67.2 IC4.7 R51.2
SIGN1736: IC5.1 R66.1
SIGN1739: C66.2 R52.1
SIGN1740: C64.2 IC5.3
SIGN1742: C70.2 IC5.8 IC5.14 R50.2
SIGN1743: IC5.9 R59.2
SIGN1745: C78.2 C436.2 IC5.4 R70.2 R72.1
SIGN1746: C68.2 IC5.7 R52.2
SIGN1753: C73.2 D4.A IC4.12 R53.2
SIGN1754: IC4.11 R53.1 R54.2
SIGN1757: C76.1 D5.C R63.2
SIGN1759: C82.2 C84.1 IC5.6 R75.1 R76.2 R79.1 R80.2
SIGN2117: IC5.11 R55.1 R56.2
SIGN2242: Q8.4 R62.2
SIGN2243: Q10.4 R64.2
SIGN2244: Q7.4 R65.2
SIGN2245: C75.2 IC4.2 L4.1 Q7.1 Q7.2 Q7.3 Q8.5 Q8.6 Q8.7 Q8.8 R71.2
SIGN2246: Q9.4 R66.2
VP_5R0_VOUT_4: C71.2 C77.1 C83.2 C85.2 C87.2 C433.2 C481.2 C482.2 C523.2 E7.1 IC4.5 IC4.13 L4.2 R69.1 R73.2 R77.2 ; off-sheet VP_5R0_VOUT_4
VP_5R0_VOUT_5: C72.2 C78.1 C84.2 C86.2 C88.2 C435.2 C483.2 C484.2 C524.2 E9.1 IC5.5 IC5.13 L5.2 R70.1 R75.2 R79.2 ; off-sheet VP_5R0_VOUT_5
VP_12R0_VIN_4: C57.2 C59.2 C61.2 C79.2 PJ4.1 Q7.5 Q7.6 Q7.7 Q7.8 R49.1 ; off-sheet VP_12R0_VIN_4
VP_12R0_VIN_5: C58.2 C60.2 C62.2 C80.2 PJ5.1 Q9.5 Q9.6 Q9.7 Q9.8 R50.1 ; off-sheet VP_12R0_VIN_5
NetIC4_15: IC4.15 R62.1
NetIC4_16: IC4.16 R61.1
NetIC5_15: IC5.15 R64.1
NetIC5_16: IC5.16 R63.1
NetR57_1: R57.1 R58.2
NetR59_1: R59.1 R60.2

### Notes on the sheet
- Unless otherwise specified
- Resistors 1/16W (1608)
- Capacitors 50V (1608)
- temperature characteristics X5R
- DC+12V
- INPUT
- (near E7) +5V 8A 100%LOAD
- (near E7) OUTPUT
- (near IC4) 200kHz
- (near E8) GND
- (near E9) +5V 8A 50%LOAD
- (near E9) OUTPUT
- (near IC5) 200kHz
- (near E10) GND

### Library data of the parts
C57 C58 = C_Dup1: as C38 on sheet 2
C59-C62 = C_Dup1: as C39 on sheet 2
C63-C66 C75 C76 C79 C80 = C_Dup1: as C41 on sheet 2
C67 C68 = C_Dup1: SQ_PART_MODEL: CON_220p; FNPARTSNAMEG: CHIP CERAMIC CAPACITOR (1608); USEINPARTSLIST: YES; OriginalSymbolOrigin: (2540,7620); CDMASTERCADCELG: C8100E; MFSOLDERINGPROP: .; TEMPCHARACTERI2: CH; MFFORMINGDIVP: KC; OUMECLASSIFICATION: セラミックコンデンサ; SIZECODESMD: 1608; MFMOUNTSYMBOLP: 80; PCODE: P03039269127; FNCLASSCODEG: P03-03; MAXGCOUNT: 1; RATEDVOLTAGE: 50; COMPONENTNAME: G36030011488; OUMEMAKER: KYC 京セラ; MFPACKAGEMETHOP: S; NOMINALCAPACITA: 220p; OUMEMAKERKATAMEI: CM105CH221J50AT; CAPACITANCETOLE: J
C69 C70 = C_Dup1: as C44 on sheet 2
C71 C72 = C_Dup1: as C45 on sheet 2
C73 C74 = C_Dup1: as C46 on sheet 2
C77 C78 = C_Dup1: SQ_PART_MODEL: CON_470n; FNPARTSNAMEG: CHIP CERAMIC CAPACITOR (1608); USEINPARTSLIST: YES; OriginalSymbolOrigin: (2540,7620); MFSOLDERINGPROP: .; TEMPCHARACTERI2: B; MFFORMINGDIVP: KC; OUMECLASSIFICATION: セラミックコンデンサ; SIZECODESMD: 1608; MFMOUNTSYMBOLP: 80; CDMASTERCADCELG: C8100E; PCODE: P03039ABG127; FNCLASSCODEG: P03-03; MAXGCOUNT: 1; RATEDVOLTAGE: 10; COMPONENTNAME: GDM030001129; OUMEMAKER: KYC 京セラ; MFPACKAGEMETHOP: S; NOMINALCAPACITA: 470n; OUMEMAKERKATAMEI: CM105B474K10AT; CAPACITANCETOLE: K
C81-C84 = C_Dup1: as C50 on sheet 2
C85 C86 = C_Dup1: as C52 on sheet 2
C87 C88 = C_Dup1: SQ_PART_MODEL: CON_1u; FNPARTSNAMEG: CHIP CERAMIC CAPACITOR (1608); PARTCOMMENT: 代表セル<KC0008> がフットプリントに登録されていません。; USEINPARTSLIST: YES; OriginalSymbolOrigin: (2540,7620); MFSOLDERINGPROP: .; TEMPCHARACTERI2: B; MFFORMINGDIVP: KC; OUMECLASSIFICATION: セラミックコンデンサ; SIZECODESMD: 1608; MFMOUNTSYMBOLP: 80; CDMASTERCADCELG: KC0008; PCODE: P03B000000ZQ; FNCLASSCODEG: P03-03; MAXGCOUNT: 1; RATEDVOLTAGE: 6.3; COMPONENTNAME: GDM030000202; OUMEMAKER: MRT 村田製作所; MFPACKAGEMETHOP: S; NOMINALCAPACITA: 1u; OUMEMAKERKATAMEI: GRM185B10J105KE21D; CAPACITANCETOLE: K
C433-C436 = C_Dup1: as C431 on sheet 2
C481-C484 C523 C524 = C_Dup1: as C479 on sheet 2
D4 D5 = D_Dup1: as D3 on sheet 2
E7-E10 = EB_Dup1: as E5 on sheet 2
IC4 IC5 = LTC7803UD: as IC3 on sheet 2
L4 L5 = L_Dup1: USEINPARTSLIST: YES; OriginalSymbolOrigin: (2540,5080); MAXGCOUNT: 1; COMPONENTNAME: L_L; OUMEMAKER: WURTH
PJ4 PJ5 = CN2_Dup1: as PJ3 on sheet 2
Q7-Q10 = MFNKR2: USEINPARTSLIST: YES; PARTNAME: TPH6R003NL; SAVEAREA0: -9199,-39,32138,22820; TIME: 18:57:44; UPDATEUSER: q91866sr; UPDATETIME: 12:36:02; SAVECOUNT: 10; OriginalSymbolOrigin: (5080,20320); MAXGCOUNT: 1; COMPONENTNAME: MFNKR2_MFNKR2
R49 R50 = R_Dup1: as R33 on sheet 2
R51 R52 = R_Dup1: SQ_PART_MODEL: RES_2.2K; FNPARTSNAMEG: CHIP RESISTOR (1608); USEINPARTSLIST: YES; OriginalSymbolOrigin: (5080,5080); MAXGCOUNT: 1; COMPONENTNAME: G36010104339; MFSOLDERINGPROP: .; OUMEMAKER: KOA ＫＯＡ; MFPACKAGEMETHOP: S; MFFORMINGDIVP: KC; MOUNTINGFORMSMD: SMD; OUMECLASSIFICATION: 表面実装用固定抵抗器; RESISTANCETOLER: F; MFMOUNTSYMBOLP: 80; POWERRATING: 63m; OUMEMAKERKATAMEI: RK73H1JTD2201F; NOMINALRESISTAN: 2.2K; NUMBEROFELEMENT: 0; VAL2: 62.5mW; CDMASTERCADCELG: DR802R; PCODE: P01042159428; FNCLASSCODEG: P01-08
R53 R55 = R_Dup1: as R35 on sheet 2
R54 R56 = R_Dup1: as R36 on sheet 2
R57 R59 = R_Dup1: SQ_PART_MODEL: RES_27K; FNPARTSNAMEG: CHIP RESISTOR (1608); USEINPARTSLIST: YES; OriginalSymbolOrigin: (5080,5080); MAXGCOUNT: 1; TOLERANCE: F; COMPONENTNAME: G36010027195; MFSOLDERINGPROP: .; OUMEMAKER: NAE 松下電子部品; MFPACKAGEMETHOP: S; MFFORMINGDIVP: KC; MOUNTINGFORMSMD: SMD; OUMECLASSIFICATION: 表面実装用固定抵抗器; ASIMVALUE: 27K; MFMOUNTSYMBOLP: 80; POWERRATING: 63m; OUMEMAKERKATAMEI: ERJ3GEYF273V; NUMBEROFELEMENT: 0; VAL2: 62.5mW; CDMASTERCADCELG: DR802R; PCODE: P01042508622; FNCLASSCODEG: P01-08
R58 R60 = R_Dup1: SQ_PART_MODEL: RES_160K; FNPARTSNAMEG: CHIP RESISTOR (1608); USEINPARTSLIST: YES; OriginalSymbolOrigin: (5080,5080); MAXGCOUNT: 1; COMPONENTNAME: G51011061108; MFSOLDERINGPROP: .; OUMEMAKER: HDK 北陸電気工業; MFPACKAGEMETHOP: S; MFFORMINGDIVP: KC; MOUNTINGFORMSMD: SMD; OUMECLASSIFICATION: 表面実装用固定抵抗器; RESISTANCETOLER: F; MFMOUNTSYMBOLP: 80; POWERRATING: 63m; OUMEMAKERKATAMEI: CR1/16 164FV; NOMINALRESISTAN: 160K; NUMBEROFELEMENT: 0; VAL2: 62.5mW; CDMASTERCADCELG: DR802R; PCODE: P01042125225; FNCLASSCODEG: P01-08
R61 R63 = R_Dup1: as R39 on sheet 2
R62 R64-R66 = R_Dup1: as R40 on sheet 2
R69 R70 = R_Dup1: SQ_PART_MODEL: RES_47K; FNPARTSNAMEG: CHIP RESISTOR (1608); USEINPARTSLIST: YES; OriginalSymbolOrigin: (5080,5080); TOLERANCE: F; ASIMVALUE: 47K; MAXGCOUNT: 1; COMPONENTNAME: G36010027102; MFSOLDERINGPROP: .; OUMEMAKER: KOA ＫＯＡ; MFPACKAGEMETHOP: S; MFFORMINGDIVP: KC; MOUNTINGFORMSMD: SMD; OUMECLASSIFICATION: 表面実装用固定抵抗器; MFMOUNTSYMBOLP: 80; POWERRATING: 63m; OUMEMAKERKATAMEI: RK73H1JTD4702F; NUMBEROFELEMENT: 0; VAL2: 62.5mW; VAL1: 47K(F); CDMASTERCADCELG: DR802R; PCODE: P01042373428; FNCLASSCODEG: P01-08
R71 R72 = R_Dup1: SQ_PART_MODEL: RES_2.4K; FNPARTSNAMEG: CHIP RESISTOR (1608); USEINPARTSLIST: YES; OriginalSymbolOrigin: (5080,5080); TOLERANCE: F; ASIMVALUE: 2.4K; PCODE: P01042166327; MAXGCOUNT: 1; COMPONENTNAME: K0100562; MFSOLDERINGPROP: .; OUMEMAKER: KAM 釜屋電機; MFPACKAGEMETHOP: S; MFFORMINGDIVP: KC; MOUNTINGFORMSMD: SMD; OUMECLASSIFICATION: 表面実装用固定抵抗器; MFMOUNTSYMBOLP: 80; POWERRATING: 63m; OUMEMAKERKATAMEI: RMC1/16-242FTP; NUMBEROFELEMENT: 0; VAL2: 62.5mW; CDMASTERCADCELG: DR802R; FNCLASSCODEG: P01-08
R73 R75 = R_Dup1: as R45 on sheet 2
R74 R76 = R_Dup1: as R46 on sheet 2
R77 R79 = R_Dup1: as R47 on sheet 2
R78 R80 = R_Dup1: as R48 on sheet 2
U?#3 = WAKU_DEF100: PLOTTIME: HH:MM; SAVEAREA0: 330961,54,387907,31546; TIME: 19:23:07; UPDATEUSER: t5459927; UPDATETIME: 15:33:39; SAVECOUNT: 6; OriginalSymbolOrigin: (10160,284480); DESIGNED: ***

## Sheet 4.SchDoc
size 420 x 297 mm
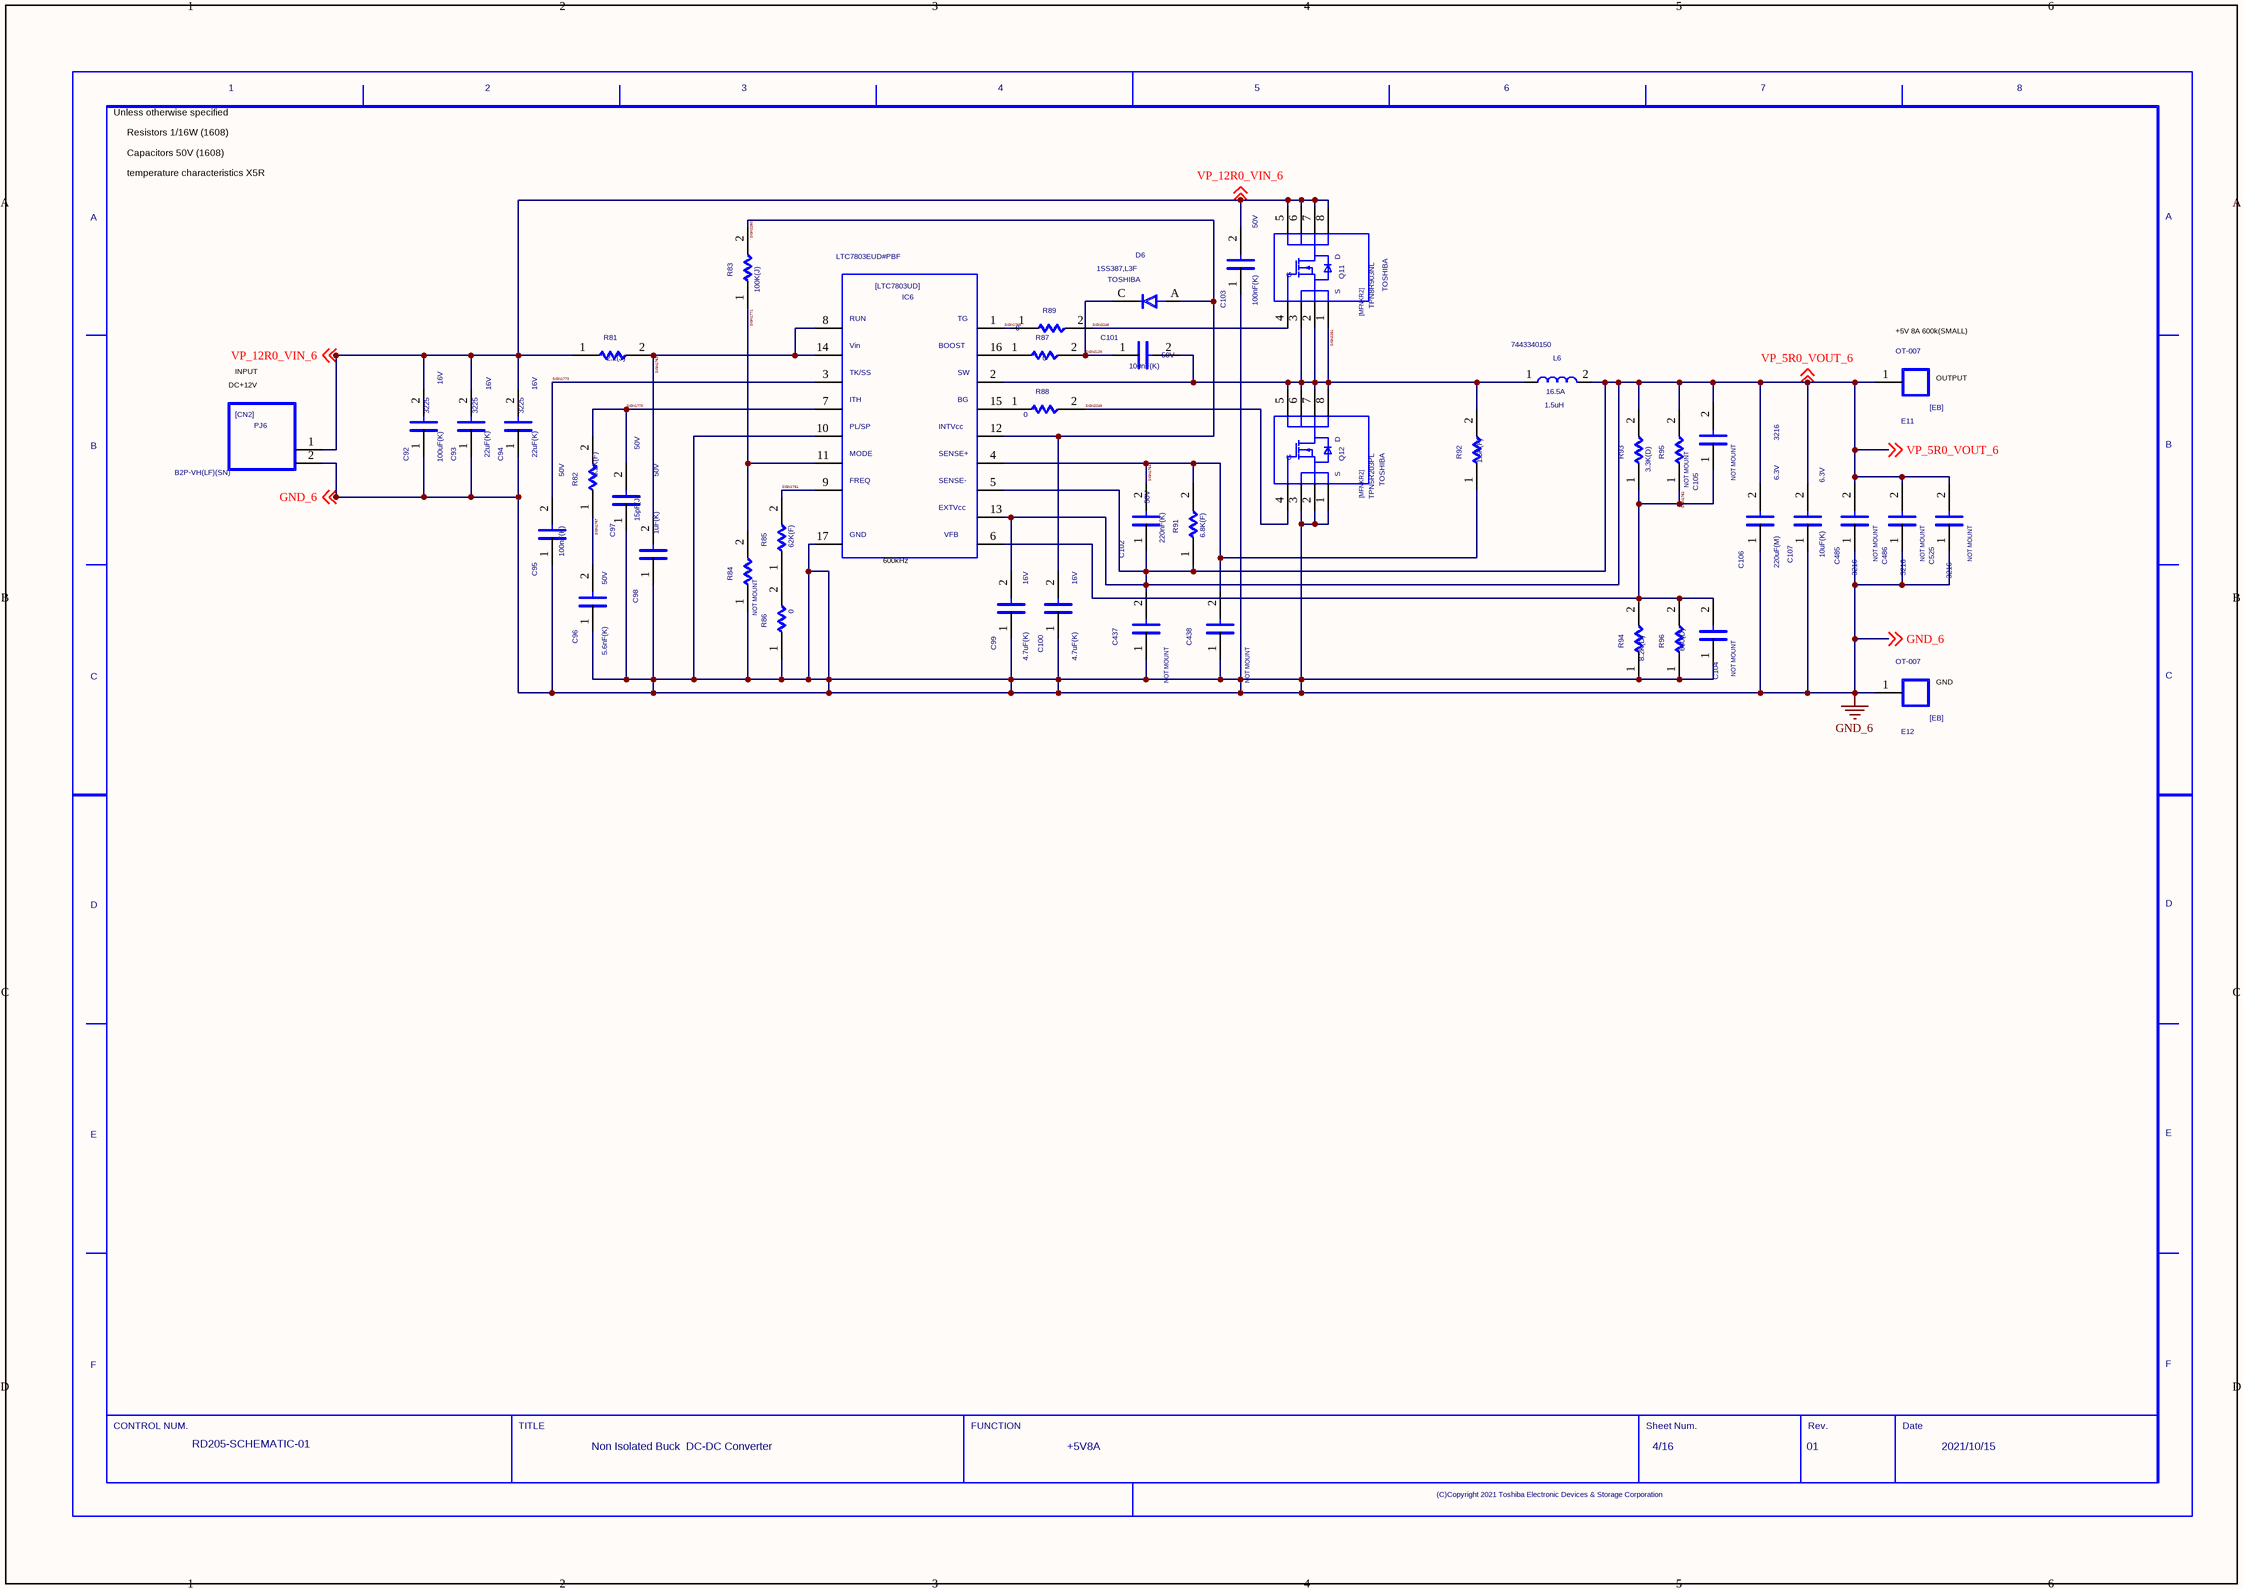
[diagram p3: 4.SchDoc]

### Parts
(Parts that share a designator on the sheet are numbered #1, #2 ... from top to bottom, then left to right.)
C92  SIZECODESMD: 3225  VAL2: 16V  VAL1: 100uF(K)  (hidden comment: C)
C93  SIZECODESMD: 3225  VAL2: 16V  VAL1: 22uF(K)  (hidden comment: C)
C94  SIZECODESMD: 3225  VAL2: 16V  VAL1: 22uF(K)  (hidden comment: C)
C95  VAL2: 50V  VAL1: 100nF(K)  (hidden comment: C)
C96  VAL2: 50V  VAL1: 5.6nF(K)  (hidden comment: C)
C97  VAL2: 50V  VAL1: 15pF(J)  (hidden comment: C)
C98  VAL2: 50V  VAL1: 1uF(K)  (hidden comment: C)
C99  VAL2: 16V  VAL1: 4.7uF(K)  (hidden comment: C)
C100  VAL2: 16V  VAL1: 4.7uF(K)  (hidden comment: C)
C101  VAL2: 50V  VAL1: 100nF(K)  (hidden comment: C)
C102  VAL2: 50V  VAL1: 220nF(K)  (hidden comment: C)
C103  VAL2: 50V  VAL1: 100nF(K)  (hidden comment: C)
C104  NOTMOUNT: NOT MOUNT  (hidden comment: C)
C105  NOTMOUNT: NOT MOUNT  (hidden comment: C)
C106  SIZECODESMD: 3216  VAL2: 6.3V  VAL1: 220uF(M)  (hidden comment: C)
C107  VAL2: 6.3V  VAL1: 10uF(K)  (hidden comment: C)
C437  NOTMOUNT: NOT MOUNT  (hidden comment: C)
C438  NOTMOUNT: NOT MOUNT  (hidden comment: C)
C485  NOTMOUNT: NOT MOUNT  SIZECODESMD: 3216  (hidden comment: C)
C486  NOTMOUNT: NOT MOUNT  SIZECODESMD: 3216  (hidden comment: C)
C525  NOTMOUNT: NOT MOUNT  SIZECODESMD: 3216  (hidden comment: C)
D6  USERCOMPTEXT3: TOSHIBA  VAL3: 1SS387,L3F  (hidden comment: D)
E11  VAL3: OT-007  (hidden comment: EB)
E12  VAL3: OT-007  (hidden comment: EB)
IC6  VAL3: LTC7803EUD#PBF  (hidden comment: LTC7803UD)
L6  VAL3: 7443340150  VAL2: 16.5A  VAL1: 1.5uH  (hidden comment: L)
PJ6  VAL3: B2P-VH(LF)(SN)  (hidden comment: CN2)
Q11  USERCOMPTEXT3: TOSHIBA  VAL3: TPN8R903NL  (hidden comment: MFNKR2)
Q12  USERCOMPTEXT3: TOSHIBA  VAL3: TPN5R203PL  (hidden comment: MFNKR2)
R81  VAL1: 2.2(J)  (hidden comment: R)
R82  VAL1: 6.2K(F)  (hidden comment: R)
R83  VAL1: 100K(J)  (hidden comment: R)
R84  NOTMOUNT: NOT MOUNT  (hidden comment: R)
R85  VAL1: 62K(F)  (hidden comment: R)
R86  VAL1: 0  (hidden comment: R)
R87  VAL1: 0  (hidden comment: R)
R88  VAL1: 0  (hidden comment: R)
R89  VAL1: 0  (hidden comment: R)
R91  VAL1: 6.8K(F)  (hidden comment: R)
R92  VAL1: 1.5K(F)  (hidden comment: R)
R93  VAL1: 3.3K(D)  (hidden comment: R)
R94  VAL1: 8.2K(D)  (hidden comment: R)
R95  NOTMOUNT: NOT MOUNT  (hidden comment: R)
R96  VAL1: 680(D)  (hidden comment: R)
U?#4  DATE: 2021/10/15  SHEETNUMBER: 4/16  TITLE: Non Isolated Buck / DC-DC Converter  REVISION: 01  DRAWINGNUMBER: RD205-SCHEMATIC-01  FUNCTION: +5V8A  (hidden comment: WAKU_DEF100)

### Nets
GND_6: C92.1 C93.1 C94.1 C95.1 C96.1 C97.1 C98.1 C99.1 C100.1 C103.1 C104.1 C106.1 C107.1 C437.1 C438.1 C485.1 C486.1 C525.1 E12.1 IC6.10 IC6.17 PJ6.2 Q12.1 Q12.2 Q12.3 R84.1 R86.1 R94.1 R96.1 ; off-sheet GND_6
SIGN1761: IC6.9 R85.2
SIGN1762: C104.2 C105.1 IC6.6 R93.1 R94.2 R95.1 R96.2
SIGN1763: C98.2 IC6.8 IC6.14 R81.2
SIGN1764: C102.2 C438.2 IC6.4 R91.2 R92.1
SIGN1765: IC6.1 R89.1
SIGN1767: C96.2 R82.1
SIGN1770: C97.2 IC6.7 R82.2
SIGN1771: IC6.11 R83.1 R84.2
SIGN1773: C95.2 IC6.3
SIGN2129: C101.1 D6.C R87.2
SIGN2248: Q11.4 R89.2
SIGN2249: Q12.4 R88.2
SIGN2250: C100.2 D6.A IC6.12 R83.2
SIGN2251: C101.2 IC6.2 L6.1 Q11.1 Q11.2 Q11.3 Q12.5 Q12.6 Q12.7 Q12.8 R92.2
VP_5R0_VOUT_6: C99.2 C102.1 C105.2 C106.2 C107.2 C437.2 C485.2 C486.2 C525.2 E11.1 IC6.5 IC6.13 L6.2 R91.1 R93.2 R95.2 ; off-sheet VP_5R0_VOUT_6
VP_12R0_VIN_6: C92.2 C93.2 C94.2 C103.2 PJ6.1 Q11.5 Q11.6 Q11.7 Q11.8 R81.1 ; off-sheet VP_12R0_VIN_6
NetIC6_15: IC6.15 R88.1
NetIC6_16: IC6.16 R87.1
NetR85_1: R85.1 R86.2

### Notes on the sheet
- Unless otherwise specified
- Resistors 1/16W (1608)
- Capacitors 50V (1608)
- temperature characteristics X5R
- DC+12V
- INPUT
- (near E11) +5V 8A 600k(SMALL)
- (near E11) OUTPUT
- (near IC6) 600kHz
- (near E12) GND

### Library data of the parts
C92 = C_Dup1: as C38 on sheet 2
C93 C94 = C_Dup1: as C39 on sheet 2
C95 C101 C103 = C_Dup1: as C41 on sheet 2
C96 = C_Dup1: SQ_PART_MODEL: CON_5.6n; FNPARTSNAMEG: CHIP CERAMIC CAPACITOR (1608); USEINPARTSLIST: YES; OriginalSymbolOrigin: (2540,7620); TOLERANCE: K; ASIMVALUE: 5.6N; MFSOLDERINGPROP: .; TEMPCHARACTERI2: B; MFFORMINGDIVP: KC; OUMECLASSIFICATION: セラミックコンデンサ; SIZECODESMD: 1608; MFMOUNTSYMBOLP: 80; CDMASTERCADCELG: C8100E; PCODE: P03039100222; FNCLASSCODEG: P03-03; MAXGCOUNT: 1; RATEDVOLTAGE: 50; COMPONENTNAME: G36030011068; OUMEMAKER: MRT 村田製作所; MFPACKAGEMETHOP: S; OUMEMAKERKATAMEI: GRM39B562K50PT
C97 = C_Dup1: SQ_PART_MODEL: CON_15p; FNPARTSNAMEG: CHIP CERAMIC CAPACITOR (1608); USEINPARTSLIST: YES; OriginalSymbolOrigin: (2540,7620); MFSOLDERINGPROP: .; TEMPCHARACTERI2: CH; MFFORMINGDIVP: KC; OUMECLASSIFICATION: セラミックコンデンサ; SIZECODESMD: 1608; MFMOUNTSYMBOLP: 80; CDMASTERCADCELG: C8100E; PCODE: P03039230226; FNCLASSCODEG: P03-03; MAXGCOUNT: 1; RATEDVOLTAGE: 50; COMPONENTNAME: G36030104043; OUMEMAKER: MRT 村田製作所; MFPACKAGEMETHOP: S; NOMINALCAPACITA: 15p; OUMEMAKERKATAMEI: GRM39CH150J50PT; CAPACITANCETOLE: J
C98 = C_Dup1: as C44 on sheet 2
C99 = C_Dup1: as C45 on sheet 2
C100 = C_Dup1: as C46 on sheet 2
C102 = C_Dup1: as C48 on sheet 2
C104 C105 = C_Dup1: as C50 on sheet 2
C106 = C_Dup1: as C52 on sheet 2
C107 = C_Dup1: as C53 on sheet 2
C437 C438 = C_Dup1: as C431 on sheet 2
C485 C486 C525 = C_Dup1: as C479 on sheet 2
D6 = D_Dup1: as D3 on sheet 2
E11 E12 = EB_Dup1: as E5 on sheet 2
IC6 = LTC7803UD: as IC3 on sheet 2
L6 = L_Dup1: USEINPARTSLIST: YES; PARTNAME: 7443340068; OriginalSymbolOrigin: (2540,5080); MAXGCOUNT: 1; COMPONENTNAME: L_L; OUMEMAKER: WURTH
PJ6 = CN2_Dup1: as PJ3 on sheet 2
Q11 Q12 = MFNKR2: as Q5 on sheet 2
R81 = R_Dup1: as R33 on sheet 2
R82 = R_Dup1: SQ_PART_MODEL: RES_6.2K; FNPARTSNAMEG: CHIP RESISTOR (1608); USEINPARTSLIST: YES; OriginalSymbolOrigin: (5080,5080); TOLERANCE: F; ASIMVALUE: 6.2K; MAXGCOUNT: 1; COMPONENTNAME: G36010027379; MFSOLDERINGPROP: .; OUMEMAKER: KOA ＫＯＡ; MFPACKAGEMETHOP: S; MFFORMINGDIVP: KC; MOUNTINGFORMSMD: SMD; OUMECLASSIFICATION: 表面実装用固定抵抗器; MFMOUNTSYMBOLP: 80; POWERRATING: 63m; OUMEMAKERKATAMEI: RK73H1JTD6201F; NUMBEROFELEMENT: 0; VAL2: 62.5mW; CDMASTERCADCELG: DR802R; PCODE: P01042419423; FNCLASSCODEG: P01-08
R83 = R_Dup1: as R35 on sheet 2
R84 = R_Dup1: as R36 on sheet 2
R85 = R_Dup1: as R37 on sheet 2
R86 = R_Dup1: as R38 on sheet 2
R87 = R_Dup1: as R39 on sheet 2
R88 R89 = R_Dup1: as R40 on sheet 2
R91 = R_Dup1: SQ_PART_MODEL: RES_6.8K; FNPARTSNAMEG: CHIP RESISTOR (1608); USEINPARTSLIST: YES; OriginalSymbolOrigin: (5080,5080); MAXGCOUNT: 1; COMPONENTNAME: G5101105R107; MFSOLDERINGPROP: .; OUMEMAKER: NAE 松下電子部品; MFPACKAGEMETHOP: S; MFFORMINGDIVP: KC; MOUNTINGFORMSMD: SMD; OUMECLASSIFICATION: 表面実装用固定抵抗器; RESISTANCETOLER: F; MFMOUNTSYMBOLP: 80; POWERRATING: 63m; OUMEMAKERKATAMEI: ERJ3GEYF682V; NOMINALRESISTAN: 6.8K; NUMBEROFELEMENT: 0; VAL2: 62.5mW; CDMASTERCADCELG: DR802R; PCODE: P01042424625; FNCLASSCODEG: P01-08
R92 = R_Dup1: as R42 on sheet 2
R93 = R_Dup1: as R45 on sheet 2
R94 = R_Dup1: as R46 on sheet 2
R95 = R_Dup1: as R47 on sheet 2
R96 = R_Dup1: as R48 on sheet 2
U?#4 = WAKU_DEF100: as U?#3 on sheet 3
